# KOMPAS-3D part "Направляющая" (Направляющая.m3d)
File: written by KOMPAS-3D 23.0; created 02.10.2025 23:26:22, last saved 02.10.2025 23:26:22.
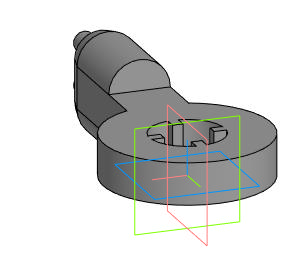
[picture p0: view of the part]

Document properties: Автор: Inspektor_Kot; Полное имя файла: I:\Autodesk Inventor Projects\ИМ-ИТ ЦД\Вариант 10\Направляющая.m3d

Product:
- Part/product: Направляющая

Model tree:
1. Эскиз:1  (with: Элемент выдавливания:3, Элемент выдавливания:7)
2. Элемент выдавливания:1  (with: Элемент выдавливания:7)
     Расстояние 1 = -20
3. Эскиз:2  (with: Элемент выдавливания:1, Элемент выдавливания:7)
4. Элемент выдавливания:2
     Расстояние 1 = 10; Угол 1 = 15
5. Элемент выдавливания:3  (with: Элемент выдавливания:2)
     Расстояние 1 = 40
6. Эскиз:4  (with: Элемент выдавливания:3)
7. Элемент выдавливания:4
     Расстояние 1 = 16
8. Эскиз:5  (with: Элемент выдавливания:4, Элемент выдавливания:6, Элемент выдавливания:3, Фаска:2)
9. Элемент выдавливания:5  (with: Элемент выдавливания:4)
     Расстояние 1 = -20

Referenced files in I:\Autodesk Inventor Projects\ИМ-ИТ ЦД\Вариант 10\: Прибор контроля заготовок..a3d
